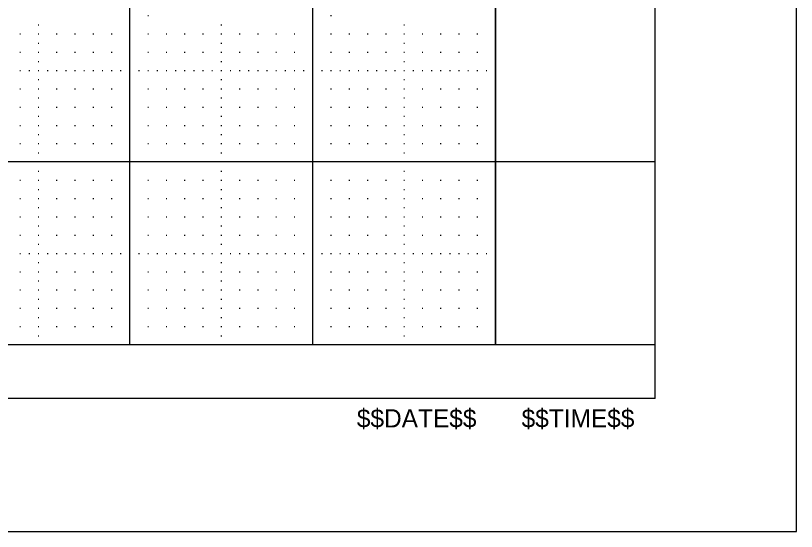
# Model space of a CAD drawing. Extents: x -1.3 to 32.7, y -0.7 to 21.3.
# Drawn here: x 28.467 to 32.737, y -0.727 to 2.093 of the extents above; entities that cross this region are included whole.
import ezdxf

# ---------------------------------------------------------------- set-up
doc = ezdxf.new("R2010")
doc.units = 0
for name, color, linetype in [('Level 1', 7, 'Continuous'), ('Level 4', 7, 'Continuous'), ('Level 48', 7, 'Continuous'), ('Level 5', 7, 'Continuous'), ('Level 63', 7, 'Continuous'), ('R_Border_Dark', 7, 'Continuous')]:
    doc.layers.add(name, color=color, linetype=linetype)

msp = doc.modelspace()

# ---------------------------------------------------------------- linework, layer by layer
at = {"layer": 'Level 1'}
for q in [(31.9643, 20.545), (0.3463, -0.001)]:
    msp.add_line((31.9643, -0.001), q, dxfattribs=at)
at = {"layer": 'Level 4'}
msp.add_line((31.9643, 0.293), (0.3463, 0.293), dxfattribs=at)
at = {"layer": 'Level 5'}
for p, q in [((29.1898, 2.093), (29.1948, 2.093)), ((30.1898, 2.093), (30.1948, 2.093)), ((28.5898, 2.043), (28.5948, 2.043)), ((29.5898, 2.043), (29.5948, 2.043)), ((30.5898, 2.043), (30.5948, 2.043)), ((28.4898, 1.993), (28.4948, 1.993)), ((28.5898, 1.993), (28.5948, 1.993)), ((28.6898, 1.993), (28.6948, 1.993)), ((28.7898, 1.993), (28.7948, 1.993)), ((28.8898, 1.993), (28.8948, 1.993)), ((28.9898, 1.993), (28.9948, 1.993)), ((29.1898, 1.993), (29.1948, 1.993)), ((29.2898, 1.993), (29.2948, 1.993)), ((29.3898, 1.993), (29.3948, 1.993)), ((29.4898, 1.993), (29.4948, 1.993)), ((29.5898, 1.993), (29.5948, 1.993)), ((29.6898, 1.993), (29.6948, 1.993)), ((29.7898, 1.993), (29.7948, 1.993)), ((29.8898, 1.993), (29.8948, 1.993)), ((29.9898, 1.993), (29.9948, 1.993)), ((30.1898, 1.993), (30.1948, 1.993)), ((30.2898, 1.993), (30.2948, 1.993)), ((30.3898, 1.993), (30.3948, 1.993)), ((30.4898, 1.993), (30.4948, 1.993)), ((30.5898, 1.993), (30.5948, 1.993)), ((30.6898, 1.993), (30.6948, 1.993)), ((30.7898, 1.993), (30.7948, 1.993)), ((30.8898, 1.993), (30.8948, 1.993)), ((30.9898, 1.993), (30.9948, 1.993)), ((28.5898, 1.943), (28.5948, 1.943)), ((29.5898, 1.943), (29.5948, 1.943)), ((30.5898, 1.943), (30.5948, 1.943)), ((28.4898, 1.893), (28.4948, 1.893)), ((28.5898, 1.893), (28.5948, 1.893)), ((28.6898, 1.893), (28.6948, 1.893)), ((28.7898, 1.893), (28.7948, 1.893)), ((28.8898, 1.893), (28.8948, 1.893)), ((28.9898, 1.893), (28.9948, 1.893)), ((29.1898, 1.893), (29.1948, 1.893)), ((29.2898, 1.893), (29.2948, 1.893)), ((29.3898, 1.893), (29.3948, 1.893)), ((29.4898, 1.893), (29.4948, 1.893)), ((29.5898, 1.893), (29.5948, 1.893)), ((29.6898, 1.893), (29.6948, 1.893)), ((29.7898, 1.893), (29.7948, 1.893)), ((29.8898, 1.893), (29.8948, 1.893)), ((29.9898, 1.893), (29.9948, 1.893)), ((30.1898, 1.893), (30.1948, 1.893)), ((30.2898, 1.893), (30.2948, 1.893)), ((30.3898, 1.893), (30.3948, 1.893)), ((30.4898, 1.893), (30.4948, 1.893)), ((30.5898, 1.893), (30.5948, 1.893)), ((30.6898, 1.893), (30.6948, 1.893)), ((30.7898, 1.893), (30.7948, 1.893)), ((30.8898, 1.893), (30.8948, 1.893)), ((30.9898, 1.893), (30.9948, 1.893)), ((28.5898, 1.843), (28.5948, 1.843)), ((29.5898, 1.843), (29.5948, 1.843)), ((30.5898, 1.843), (30.5948, 1.843)), ((28.4898, 1.793), (28.4948, 1.793)), ((28.5398, 1.793), (28.5448, 1.793)), ((28.5898, 1.793), (28.5948, 1.793)), ((28.6398, 1.793), (28.6448, 1.793)), ((28.6898, 1.793), (28.6948, 1.793)), ((28.7398, 1.793), (28.7448, 1.793)), ((28.7898, 1.793), (28.7948, 1.793)), ((28.8398, 1.793), (28.8448, 1.793)), ((28.8898, 1.793), (28.8948, 1.793)), ((28.9398, 1.793), (28.9448, 1.793)), ((28.9898, 1.793), (28.9948, 1.793)), ((29.0398, 1.793), (29.0448, 1.793)), ((29.1398, 1.793), (29.1448, 1.793)), ((29.1898, 1.793), (29.1948, 1.793)), ((29.2398, 1.793), (29.2448, 1.793)), ((29.2898, 1.793), (29.2948, 1.793)), ((29.3398, 1.793), (29.3448, 1.793)), ((29.3898, 1.793), (29.3948, 1.793)), ((29.4398, 1.793), (29.4448, 1.793)), ((29.4898, 1.793), (29.4948, 1.793)), ((29.5398, 1.793), (29.5448, 1.793)), ((29.5898, 1.793), (29.5948, 1.793)), ((29.6398, 1.793), (29.6448, 1.793)), ((29.6898, 1.793), (29.6948, 1.793)), ((29.7398, 1.793), (29.7448, 1.793)), ((29.7898, 1.793), (29.7948, 1.793)), ((29.8398, 1.793), (29.8448, 1.793)), ((29.8898, 1.793), (29.8948, 1.793)), ((29.9398, 1.793), (29.9448, 1.793)), ((29.9898, 1.793), (29.9948, 1.793)), ((30.0398, 1.793), (30.0448, 1.793)), ((30.1398, 1.793), (30.1448, 1.793)), ((30.1898, 1.793), (30.1948, 1.793)), ((30.2398, 1.793), (30.2448, 1.793)), ((30.2898, 1.793), (30.2948, 1.793)), ((30.3398, 1.793), (30.3448, 1.793)), ((30.3898, 1.793), (30.3948, 1.793)), ((30.4398, 1.793), (30.4448, 1.793)), ((30.4898, 1.793), (30.4948, 1.793)), ((30.5398, 1.793), (30.5448, 1.793)), ((30.5898, 1.793), (30.5948, 1.793)), ((30.6398, 1.793), (30.6448, 1.793)), ((30.6898, 1.793), (30.6948, 1.793)), ((30.7398, 1.793), (30.7448, 1.793)), ((30.7898, 1.793), (30.7948, 1.793)), ((30.8398, 1.793), (30.8448, 1.793)), ((30.8898, 1.793), (30.8948, 1.793)), ((30.9398, 1.793), (30.9448, 1.793)), ((30.9898, 1.793), (30.9948, 1.793)), ((31.0398, 1.793), (31.0448, 1.793)), ((28.5898, 1.743), (28.5948, 1.743)), ((29.5898, 1.743), (29.5948, 1.743)), ((30.5898, 1.743), (30.5948, 1.743)), ((28.4898, 1.693), (28.4948, 1.693)), ((28.5898, 1.693), (28.5948, 1.693)), ((28.6898, 1.693), (28.6948, 1.693)), ((28.7898, 1.693), (28.7948, 1.693)), ((28.8898, 1.693), (28.8948, 1.693)), ((28.9898, 1.693), (28.9948, 1.693)), ((29.1898, 1.693), (29.1948, 1.693)), ((29.2898, 1.693), (29.2948, 1.693)), ((29.3898, 1.693), (29.3948, 1.693)), ((29.4898, 1.693), (29.4948, 1.693)), ((29.5898, 1.693), (29.5948, 1.693)), ((29.6898, 1.693), (29.6948, 1.693)), ((29.7898, 1.693), (29.7948, 1.693)), ((29.8898, 1.693), (29.8948, 1.693)), ((29.9898, 1.693), (29.9948, 1.693)), ((30.1898, 1.693), (30.1948, 1.693)), ((30.2898, 1.693), (30.2948, 1.693)), ((30.3898, 1.693), (30.3948, 1.693)), ((30.4898, 1.693), (30.4948, 1.693)), ((30.5898, 1.693), (30.5948, 1.693)), ((30.6898, 1.693), (30.6948, 1.693)), ((30.7898, 1.693), (30.7948, 1.693)), ((30.8898, 1.693), (30.8948, 1.693)), ((30.9898, 1.693), (30.9948, 1.693)), ((28.5898, 1.643), (28.5948, 1.643)), ((29.5898, 1.643), (29.5948, 1.643)), ((30.5898, 1.643), (30.5948, 1.643)), ((28.4898, 1.593), (28.4948, 1.593)), ((28.5898, 1.593), (28.5948, 1.593)), ((28.6898, 1.593), (28.6948, 1.593)), ((28.7898, 1.593), (28.7948, 1.593)), ((28.8898, 1.593), (28.8948, 1.593)), ((28.9898, 1.593), (28.9948, 1.593)), ((29.1898, 1.593), (29.1948, 1.593)), ((29.2898, 1.593), (29.2948, 1.593)), ((29.3898, 1.593), (29.3948, 1.593)), ((29.4898, 1.593), (29.4948, 1.593)), ((29.5898, 1.593), (29.5948, 1.593)), ((29.6898, 1.593), (29.6948, 1.593)), ((29.7898, 1.593), (29.7948, 1.593)), ((29.8898, 1.593), (29.8948, 1.593)), ((29.9898, 1.593), (29.9948, 1.593)), ((30.1898, 1.593), (30.1948, 1.593)), ((30.2898, 1.593), (30.2948, 1.593)), ((30.3898, 1.593), (30.3948, 1.593)), ((30.4898, 1.593), (30.4948, 1.593)), ((30.5898, 1.593), (30.5948, 1.593)), ((30.6898, 1.593), (30.6948, 1.593)), ((30.7898, 1.593), (30.7948, 1.593)), ((30.8898, 1.593), (30.8948, 1.593)), ((30.9898, 1.593), (30.9948, 1.593)), ((28.5898, 1.543), (28.5948, 1.543)), ((29.5898, 1.543), (29.5948, 1.543)), ((30.5898, 1.543), (30.5948, 1.543)), ((28.4898, 1.493), (28.4948, 1.493)), ((28.5898, 1.493), (28.5948, 1.493)), ((28.6898, 1.493), (28.6948, 1.493)), ((28.7898, 1.493), (28.7948, 1.493)), ((28.8898, 1.493), (28.8948, 1.493)), ((28.9898, 1.493), (28.9948, 1.493)), ((29.1898, 1.493), (29.1948, 1.493)), ((29.2898, 1.493), (29.2948, 1.493)), ((29.3898, 1.493), (29.3948, 1.493)), ((29.4898, 1.493), (29.4948, 1.493)), ((29.5898, 1.493), (29.5948, 1.493)), ((29.6898, 1.493), (29.6948, 1.493)), ((29.7898, 1.493), (29.7948, 1.493)), ((29.8898, 1.493), (29.8948, 1.493)), ((29.9898, 1.493), (29.9948, 1.493)), ((30.1898, 1.493), (30.1948, 1.493)), ((30.2898, 1.493), (30.2948, 1.493)), ((30.3898, 1.493), (30.3948, 1.493)), ((30.4898, 1.493), (30.4948, 1.493)), ((30.5898, 1.493), (30.5948, 1.493)), ((30.6898, 1.493), (30.6948, 1.493)), ((30.7898, 1.493), (30.7948, 1.493)), ((30.8898, 1.493), (30.8948, 1.493)), ((30.9898, 1.493), (30.9948, 1.493)), ((28.5898, 1.443), (28.5948, 1.443)), ((29.5898, 1.443), (29.5948, 1.443)), ((30.5898, 1.443), (30.5948, 1.443)), ((28.4898, 1.393), (28.4948, 1.393)), ((28.5898, 1.393), (28.5948, 1.393)), ((28.6898, 1.393), (28.6948, 1.393)), ((28.7898, 1.393), (28.7948, 1.393)), ((28.8898, 1.393), (28.8948, 1.393)), ((28.9898, 1.393), (28.9948, 1.393)), ((29.1898, 1.393), (29.1948, 1.393)), ((29.2898, 1.393), (29.2948, 1.393)), ((29.3898, 1.393), (29.3948, 1.393)), ((29.4898, 1.393), (29.4948, 1.393)), ((29.5898, 1.393), (29.5948, 1.393)), ((29.6898, 1.393), (29.6948, 1.393)), ((29.7898, 1.393), (29.7948, 1.393)), ((29.8898, 1.393), (29.8948, 1.393)), ((29.9898, 1.393), (29.9948, 1.393)), ((30.1898, 1.393), (30.1948, 1.393)), ((30.2898, 1.393), (30.2948, 1.393)), ((30.3898, 1.393), (30.3948, 1.393)), ((30.4898, 1.393), (30.4948, 1.393)), ((30.5898, 1.393), (30.5948, 1.393)), ((30.6898, 1.393), (30.6948, 1.393)), ((30.7898, 1.393), (30.7948, 1.393)), ((30.8898, 1.393), (30.8948, 1.393)), ((30.9898, 1.393), (30.9948, 1.393)), ((28.5898, 1.343), (28.5948, 1.343)), ((29.5898, 1.343), (29.5948, 1.343)), ((30.5898, 1.343), (30.5948, 1.343)), ((28.5898, 1.243), (28.5948, 1.243)), ((29.5898, 1.243), (29.5948, 1.243)), ((30.5898, 1.243), (30.5948, 1.243)), ((28.4898, 1.193), (28.4948, 1.193)), ((28.5898, 1.193), (28.5948, 1.193)), ((28.6898, 1.193), (28.6948, 1.193)), ((28.7898, 1.193), (28.7948, 1.193)), ((28.8898, 1.193), (28.8948, 1.193)), ((28.9898, 1.193), (28.9948, 1.193)), ((29.1898, 1.193), (29.1948, 1.193)), ((29.2898, 1.193), (29.2948, 1.193)), ((29.3898, 1.193), (29.3948, 1.193)), ((29.4898, 1.193), (29.4948, 1.193)), ((29.5898, 1.193), (29.5948, 1.193)), ((29.6898, 1.193), (29.6948, 1.193)), ((29.7898, 1.193), (29.7948, 1.193)), ((29.8898, 1.193), (29.8948, 1.193)), ((29.9898, 1.193), (29.9948, 1.193)), ((30.1898, 1.193), (30.1948, 1.193)), ((30.2898, 1.193), (30.2948, 1.193)), ((30.3898, 1.193), (30.3948, 1.193)), ((30.4898, 1.193), (30.4948, 1.193)), ((30.5898, 1.193), (30.5948, 1.193)), ((30.6898, 1.193), (30.6948, 1.193)), ((30.7898, 1.193), (30.7948, 1.193)), ((30.8898, 1.193), (30.8948, 1.193)), ((30.9898, 1.193), (30.9948, 1.193)), ((28.5898, 1.143), (28.5948, 1.143)), ((29.5898, 1.143), (29.5948, 1.143)), ((30.5898, 1.143), (30.5948, 1.143)), ((28.4898, 1.093), (28.4948, 1.093)), ((28.5898, 1.093), (28.5948, 1.093)), ((28.6898, 1.093), (28.6948, 1.093)), ((28.7898, 1.093), (28.7948, 1.093)), ((28.8898, 1.093), (28.8948, 1.093)), ((28.9898, 1.093), (28.9948, 1.093)), ((29.1898, 1.093), (29.1948, 1.093)), ((29.2898, 1.093), (29.2948, 1.093)), ((29.3898, 1.093), (29.3948, 1.093)), ((29.4898, 1.093), (29.4948, 1.093)), ((29.5898, 1.093), (29.5948, 1.093)), ((29.6898, 1.093), (29.6948, 1.093)), ((29.7898, 1.093), (29.7948, 1.093)), ((29.8898, 1.093), (29.8948, 1.093)), ((29.9898, 1.093), (29.9948, 1.093)), ((30.1898, 1.093), (30.1948, 1.093)), ((30.2898, 1.093), (30.2948, 1.093)), ((30.3898, 1.093), (30.3948, 1.093)), ((30.4898, 1.093), (30.4948, 1.093)), ((30.5898, 1.093), (30.5948, 1.093)), ((30.6898, 1.093), (30.6948, 1.093)), ((30.7898, 1.093), (30.7948, 1.093)), ((30.8898, 1.093), (30.8948, 1.093)), ((30.9898, 1.093), (30.9948, 1.093)), ((28.5898, 1.043), (28.5948, 1.043)), ((29.5898, 1.043), (29.5948, 1.043)), ((30.5898, 1.043), (30.5948, 1.043)), ((28.4898, 0.993), (28.4948, 0.993)), ((28.5898, 0.993), (28.5948, 0.993)), ((28.6898, 0.993), (28.6948, 0.993)), ((28.7898, 0.993), (28.7948, 0.993)), ((28.8898, 0.993), (28.8948, 0.993)), ((28.9898, 0.993), (28.9948, 0.993)), ((29.1898, 0.993), (29.1948, 0.993)), ((29.2898, 0.993), (29.2948, 0.993)), ((29.3898, 0.993), (29.3948, 0.993)), ((29.4898, 0.993), (29.4948, 0.993)), ((29.5898, 0.993), (29.5948, 0.993)), ((29.6898, 0.993), (29.6948, 0.993)), ((29.7898, 0.993), (29.7948, 0.993)), ((29.8898, 0.993), (29.8948, 0.993)), ((29.9898, 0.993), (29.9948, 0.993)), ((30.1898, 0.993), (30.1948, 0.993)), ((30.2898, 0.993), (30.2948, 0.993)), ((30.3898, 0.993), (30.3948, 0.993)), ((30.4898, 0.993), (30.4948, 0.993)), ((30.5898, 0.993), (30.5948, 0.993)), ((30.6898, 0.993), (30.6948, 0.993)), ((30.7898, 0.993), (30.7948, 0.993)), ((30.8898, 0.993), (30.8948, 0.993)), ((30.9898, 0.993), (30.9948, 0.993)), ((28.5898, 0.943), (28.5948, 0.943)), ((29.5898, 0.943), (29.5948, 0.943)), ((30.5898, 0.943), (30.5948, 0.943)), ((28.4898, 0.893), (28.4948, 0.893)), ((28.5898, 0.893), (28.5948, 0.893)), ((28.6898, 0.893), (28.6948, 0.893)), ((28.7898, 0.893), (28.7948, 0.893)), ((28.8898, 0.893), (28.8948, 0.893)), ((28.9898, 0.893), (28.9948, 0.893)), ((29.1898, 0.893), (29.1948, 0.893)), ((29.2898, 0.893), (29.2948, 0.893)), ((29.3898, 0.893), (29.3948, 0.893)), ((29.4898, 0.893), (29.4948, 0.893)), ((29.5898, 0.893), (29.5948, 0.893)), ((29.6898, 0.893), (29.6948, 0.893)), ((29.7898, 0.893), (29.7948, 0.893)), ((29.8898, 0.893), (29.8948, 0.893)), ((29.9898, 0.893), (29.9948, 0.893)), ((30.1898, 0.893), (30.1948, 0.893)), ((30.2898, 0.893), (30.2948, 0.893)), ((30.3898, 0.893), (30.3948, 0.893)), ((30.4898, 0.893), (30.4948, 0.893)), ((30.5898, 0.893), (30.5948, 0.893)), ((30.6898, 0.893), (30.6948, 0.893)), ((30.7898, 0.893), (30.7948, 0.893)), ((30.8898, 0.893), (30.8948, 0.893)), ((30.9898, 0.893), (30.9948, 0.893)), ((28.5898, 0.843), (28.5948, 0.843)), ((29.5898, 0.843), (29.5948, 0.843)), ((30.5898, 0.843), (30.5948, 0.843)), ((28.4898, 0.793), (28.4948, 0.793)), ((28.5398, 0.793), (28.5448, 0.793)), ((28.5898, 0.793), (28.5948, 0.793)), ((28.6398, 0.793), (28.6448, 0.793)), ((28.6898, 0.793), (28.6948, 0.793)), ((28.7398, 0.793), (28.7448, 0.793)), ((28.7898, 0.793), (28.7948, 0.793)), ((28.8398, 0.793), (28.8448, 0.793)), ((28.8898, 0.793), (28.8948, 0.793)), ((28.9398, 0.793), (28.9448, 0.793)), ((28.9898, 0.793), (28.9948, 0.793)), ((29.0398, 0.793), (29.0448, 0.793)), ((29.1398, 0.793), (29.1448, 0.793)), ((29.1898, 0.793), (29.1948, 0.793)), ((29.2398, 0.793), (29.2448, 0.793)), ((29.2898, 0.793), (29.2948, 0.793)), ((29.3398, 0.793), (29.3448, 0.793)), ((29.3898, 0.793), (29.3948, 0.793)), ((29.4398, 0.793), (29.4448, 0.793)), ((29.4898, 0.793), (29.4948, 0.793)), ((29.5398, 0.793), (29.5448, 0.793)), ((29.5898, 0.793), (29.5948, 0.793)), ((29.6398, 0.793), (29.6448, 0.793)), ((29.6898, 0.793), (29.6948, 0.793)), ((29.7398, 0.793), (29.7448, 0.793)), ((29.7898, 0.793), (29.7948, 0.793)), ((29.8398, 0.793), (29.8448, 0.793)), ((29.8898, 0.793), (29.8948, 0.793)), ((29.9398, 0.793), (29.9448, 0.793)), ((29.9898, 0.793), (29.9948, 0.793)), ((30.0398, 0.793), (30.0448, 0.793)), ((30.1398, 0.793), (30.1448, 0.793)), ((30.1898, 0.793), (30.1948, 0.793)), ((30.2398, 0.793), (30.2448, 0.793)), ((30.2898, 0.793), (30.2948, 0.793)), ((30.3398, 0.793), (30.3448, 0.793)), ((30.3898, 0.793), (30.3948, 0.793)), ((30.4398, 0.793), (30.4448, 0.793)), ((30.4898, 0.793), (30.4948, 0.793)), ((30.5398, 0.793), (30.5448, 0.793)), ((30.5898, 0.793), (30.5948, 0.793)), ((30.6398, 0.793), (30.6448, 0.793)), ((30.6898, 0.793), (30.6948, 0.793)), ((30.7398, 0.793), (30.7448, 0.793)), ((30.7898, 0.793), (30.7948, 0.793)), ((30.8398, 0.793), (30.8448, 0.793)), ((30.8898, 0.793), (30.8948, 0.793)), ((30.9398, 0.793), (30.9448, 0.793)), ((30.9898, 0.793), (30.9948, 0.793)), ((31.0398, 0.793), (31.0448, 0.793)), ((28.5898, 0.743), (28.5948, 0.743)), ((29.5898, 0.743), (29.5948, 0.743)), ((30.5898, 0.743), (30.5948, 0.743)), ((28.4898, 0.693), (28.4948, 0.693)), ((28.5898, 0.693), (28.5948, 0.693)), ((28.6898, 0.693), (28.6948, 0.693)), ((28.7898, 0.693), (28.7948, 0.693)), ((28.8898, 0.693), (28.8948, 0.693)), ((28.9898, 0.693), (28.9948, 0.693)), ((29.1898, 0.693), (29.1948, 0.693)), ((29.2898, 0.693), (29.2948, 0.693)), ((29.3898, 0.693), (29.3948, 0.693)), ((29.4898, 0.693), (29.4948, 0.693)), ((29.5898, 0.693), (29.5948, 0.693)), ((29.6898, 0.693), (29.6948, 0.693)), ((29.7898, 0.693), (29.7948, 0.693)), ((29.8898, 0.693), (29.8948, 0.693)), ((29.9898, 0.693), (29.9948, 0.693)), ((30.1898, 0.693), (30.1948, 0.693)), ((30.2898, 0.693), (30.2948, 0.693)), ((30.3898, 0.693), (30.3948, 0.693)), ((30.4898, 0.693), (30.4948, 0.693)), ((30.5898, 0.693), (30.5948, 0.693)), ((30.6898, 0.693), (30.6948, 0.693)), ((30.7898, 0.693), (30.7948, 0.693)), ((30.8898, 0.693), (30.8948, 0.693)), ((30.9898, 0.693), (30.9948, 0.693)), ((28.5898, 0.643), (28.5948, 0.643)), ((29.5898, 0.643), (29.5948, 0.643)), ((30.5898, 0.643), (30.5948, 0.643)), ((28.4898, 0.593), (28.4948, 0.593)), ((28.5898, 0.593), (28.5948, 0.593)), ((28.6898, 0.593), (28.6948, 0.593)), ((28.7898, 0.593), (28.7948, 0.593)), ((28.8898, 0.593), (28.8948, 0.593)), ((28.9898, 0.593), (28.9948, 0.593)), ((29.1898, 0.593), (29.1948, 0.593)), ((29.2898, 0.593), (29.2948, 0.593)), ((29.3898, 0.593), (29.3948, 0.593)), ((29.4898, 0.593), (29.4948, 0.593)), ((29.5898, 0.593), (29.5948, 0.593)), ((29.6898, 0.593), (29.6948, 0.593)), ((29.7898, 0.593), (29.7948, 0.593)), ((29.8898, 0.593), (29.8948, 0.593)), ((29.9898, 0.593), (29.9948, 0.593)), ((30.1898, 0.593), (30.1948, 0.593)), ((30.2898, 0.593), (30.2948, 0.593)), ((30.3898, 0.593), (30.3948, 0.593)), ((30.4898, 0.593), (30.4948, 0.593)), ((30.5898, 0.593), (30.5948, 0.593)), ((30.6898, 0.593), (30.6948, 0.593)), ((30.7898, 0.593), (30.7948, 0.593)), ((30.8898, 0.593), (30.8948, 0.593)), ((30.9898, 0.593), (30.9948, 0.593)), ((28.5898, 0.543), (28.5948, 0.543)), ((29.5898, 0.543), (29.5948, 0.543)), ((30.5898, 0.543), (30.5948, 0.543)), ((28.4898, 0.493), (28.4948, 0.493)), ((28.5898, 0.493), (28.5948, 0.493)), ((28.6898, 0.493), (28.6948, 0.493)), ((28.7898, 0.493), (28.7948, 0.493)), ((28.8898, 0.493), (28.8948, 0.493)), ((28.9898, 0.493), (28.9948, 0.493)), ((29.1898, 0.493), (29.1948, 0.493)), ((29.2898, 0.493), (29.2948, 0.493)), ((29.3898, 0.493), (29.3948, 0.493)), ((29.4898, 0.493), (29.4948, 0.493)), ((29.5898, 0.493), (29.5948, 0.493)), ((29.6898, 0.493), (29.6948, 0.493)), ((29.7898, 0.493), (29.7948, 0.493)), ((29.8898, 0.493), (29.8948, 0.493)), ((29.9898, 0.493), (29.9948, 0.493)), ((30.1898, 0.493), (30.1948, 0.493)), ((30.2898, 0.493), (30.2948, 0.493)), ((30.3898, 0.493), (30.3948, 0.493)), ((30.4898, 0.493), (30.4948, 0.493)), ((30.5898, 0.493), (30.5948, 0.493)), ((30.6898, 0.493), (30.6948, 0.493)), ((30.7898, 0.493), (30.7948, 0.493)), ((30.8898, 0.493), (30.8948, 0.493)), ((30.9898, 0.493), (30.9948, 0.493)), ((28.5898, 0.443), (28.5948, 0.443)), ((29.5898, 0.443), (29.5948, 0.443)), ((30.5898, 0.443), (30.5948, 0.443)), ((28.4898, 0.393), (28.4948, 0.393)), ((28.5898, 0.393), (28.5948, 0.393)), ((28.6898, 0.393), (28.6948, 0.393)), ((28.7898, 0.393), (28.7948, 0.393)), ((28.8898, 0.393), (28.8948, 0.393)), ((28.9898, 0.393), (28.9948, 0.393)), ((29.1898, 0.393), (29.1948, 0.393)), ((29.2898, 0.393), (29.2948, 0.393)), ((29.3898, 0.393), (29.3948, 0.393)), ((29.4898, 0.393), (29.4948, 0.393)), ((29.5898, 0.393), (29.5948, 0.393)), ((29.6898, 0.393), (29.6948, 0.393)), ((29.7898, 0.393), (29.7948, 0.393)), ((29.8898, 0.393), (29.8948, 0.393)), ((29.9898, 0.393), (29.9948, 0.393)), ((30.1898, 0.393), (30.1948, 0.393)), ((30.2898, 0.393), (30.2948, 0.393)), ((30.3898, 0.393), (30.3948, 0.393)), ((30.4898, 0.393), (30.4948, 0.393)), ((30.5898, 0.393), (30.5948, 0.393)), ((30.6898, 0.393), (30.6948, 0.393)), ((30.7898, 0.393), (30.7948, 0.393)), ((30.8898, 0.393), (30.8948, 0.393)), ((30.9898, 0.393), (30.9948, 0.393)), ((28.5898, 0.343), (28.5948, 0.343)), ((29.5898, 0.343), (29.5948, 0.343)), ((30.5898, 0.343), (30.5948, 0.343))]:
    msp.add_line(p, q, dxfattribs=at)
at = {"layer": 'Level 63'}
msp.add_lwpolyline([(-1.263, -0.727), (32.737, -0.727), (32.737, 21.273), (-1.263, 21.273)], close=True, dxfattribs=at)
msp.add_lwpolyline([(31.0923, 10.293), (31.0923, 0.293), (1.0923, 0.293), (1.0923, 8.293)], dxfattribs=at)
at = {"layer": 'R_Border_Dark'}
for p, q in [((29.0923, 0.293), (29.0923, 10.293)), ((30.0923, 0.293), (30.0923, 10.293)), ((31.0923, 0.293), (31.0923, 10.293)), ((31.9643, 1.293), (0.3463, 1.293))]:
    msp.add_line(p, q, dxfattribs=at)
msp.add_lwpolyline([(31.0923, 10.293), (31.0923, 0.293), (1.0923, 0.293), (1.0923, 8.293)], dxfattribs=at)

# ---------------------------------------------------------------- texts
at = {"layer": 'Level 48'}
for s, p in [('$$DATE$$', (30.3333, -0.159)), ('$$TIME$$', (31.2343, -0.159))]:
    msp.add_text(s, height=0.1, dxfattribs=at).set_placement(p)

doc.saveas('drawing.dxf')
